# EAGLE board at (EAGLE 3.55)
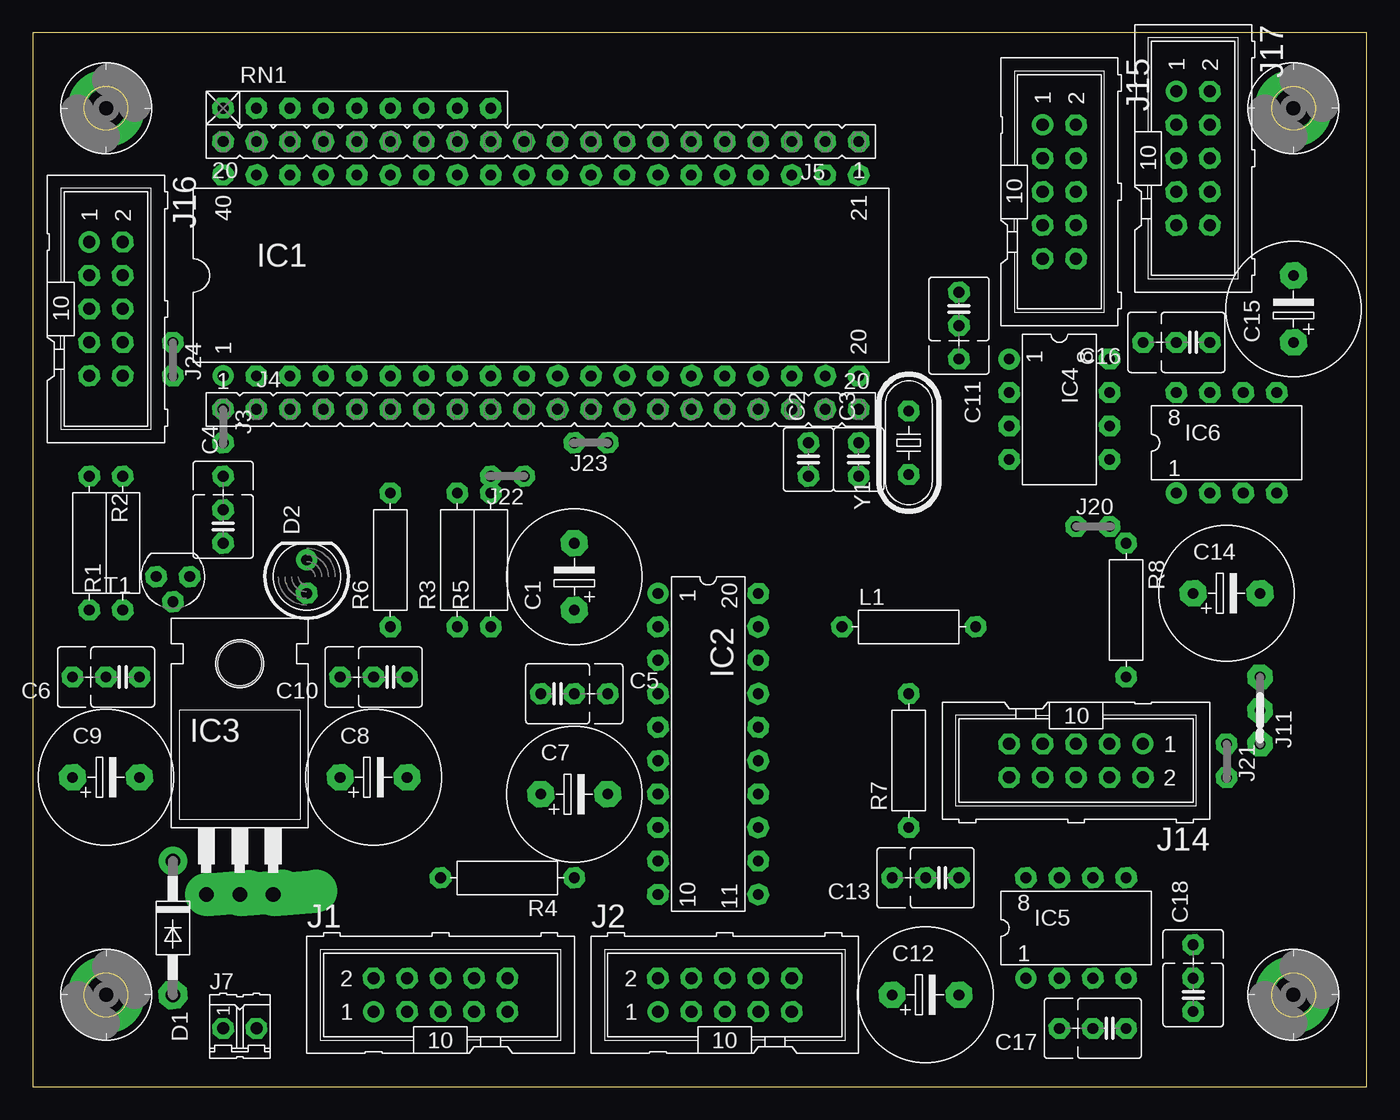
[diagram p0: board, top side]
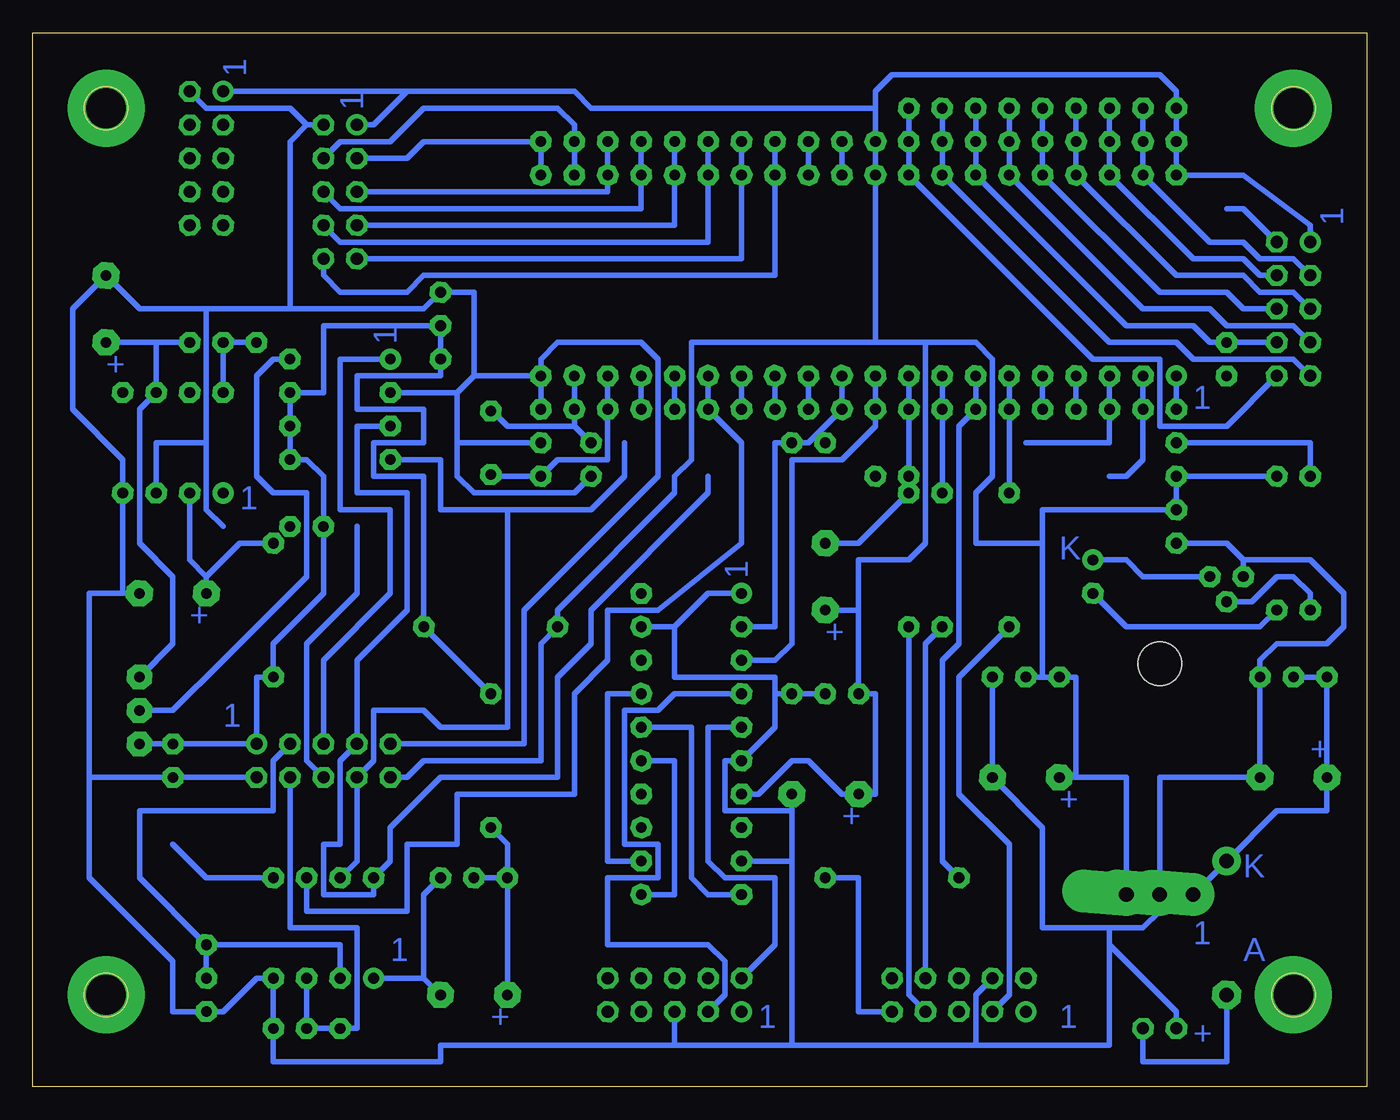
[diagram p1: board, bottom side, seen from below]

Size 101.27 x 80 mm. Coordinates in mm from the lower left corner, seen from the top.
Outline: 0,0 101.27,0 101.27,80 0,80 0,0
Copper layers used: Bottom

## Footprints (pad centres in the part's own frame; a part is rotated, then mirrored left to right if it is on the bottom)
-5 = drill 0.813 pad 2.007 octagon:  -2.54,0;  2.54,0
,5-4 = drill 0.813 pad 1.6 octagon:  -1.27,0;  1.27,0
,5/5-5 = drill 0.813 pad 1.6 octagon:  -2.54,0;  2.54,0;  0,0
41-10 = drill 1.118 pad 2.159 octagon:  5.08,0 | drill 1.118 pad 2.159 round:  -5.08,0
D5 = drill 0.813 pad 1.6 octagon:  -1.27,0 | drill 0.813 pad 1.6 round:  1.27,0
L40 = drill 0.813 pad 1.6 round:  -24.13,-7.62 | drill 0.813 pad 1.6 octagon:  -21.59,-7.62;  -19.05,-7.62;  -16.51,-7.62;  -13.97,-7.62;  -11.43,-7.62;  -8.89,-7.62;  -6.35,-7.62;  -3.81,-7.62;  -1.27,-7.62;  1.27,-7.62;  3.81,-7.62;  6.35,-7.62;  8.89,-7.62;  11.43,-7.62;  13.97,-7.62;  16.51,-7.62;  19.05,-7.62;  21.59,-7.62;  24.13,-7.62;  24.13,7.62;  21.59,7.62;  19.05,7.62;  16.51,7.62;  13.97,7.62;  11.43,7.62;  8.89,7.62;  6.35,7.62;  3.81,7.62;  1.27,7.62;  -1.27,7.62;  -3.81,7.62;  -6.35,7.62;  -8.89,7.62;  -11.43,7.62;  -13.97,7.62;  -16.51,7.62;  -19.05,7.62;  -21.59,7.62;  -24.13,7.62
L20 = drill 0.813 pad 1.6 round:  -11.43,-3.81 | drill 0.813 pad 1.6 octagon:  -8.89,-3.81;  -6.35,-3.81;  -3.81,-3.81;  -1.27,-3.81;  1.27,-3.81;  3.81,-3.81;  6.35,-3.81;  8.89,-3.81;  11.43,-3.81;  11.43,3.81;  8.89,3.81;  6.35,3.81;  3.81,3.81;  1.27,3.81;  -1.27,3.81;  -3.81,3.81;  -6.35,3.81;  -8.89,3.81;  -11.43,3.81
220H = drill 1.118 pad 3.251 offset:  -2.54,-6.35;  0,-6.35;  2.54,-6.35 | hole 3.302: 0,11.176
L08 = drill 0.813 pad 1.6 round:  -3.81,-3.81 | drill 0.813 pad 1.6 octagon:  -1.27,-3.81;  1.27,-3.81;  3.81,-3.81;  3.81,3.81;  1.27,3.81;  -1.27,3.81;  -3.81,3.81
10 = drill 0.914 pad 1.6 round:  -5.08,-1.27 | drill 0.914 pad 1.6 octagon:  -5.08,1.27;  -2.54,-1.27;  -2.54,1.27;  0,-1.27;  0,1.27;  2.54,-1.27;  2.54,1.27;  5.08,-1.27;  5.08,1.27
 = drill 0.813 pad 1.6 octagon:  -2.54,0;  0,0
20 = drill 0.813 pad 1.6 octagon:  -24.13,0;  -21.59,0;  -19.05,0;  -16.51,0;  -13.97,0;  -11.43,0;  -8.89,0;  -6.35,0;  -3.81,0;  -1.27,0;  1.27,0;  3.81,0;  6.35,0;  8.89,0;  11.43,0;  13.97,0;  16.51,0;  19.05,0;  21.59,0;  24.13,0
P = drill 0.914 pad 1.6 octagon:  -1.27,0;  1.27,0
C = drill 0.813 pad 1.905 octagon:  -5.08,0;  -2.54,0;  0,0
10' = drill 0.813 pad 1.6 octagon:  -5.08,0;  5.08,0
3,0-P = drill 3.023 pad 5.842 round: 0 0,0
-9 = drill 0.813 pad 1.6 octagon:  -10.16,0;  -7.62,0;  -5.08,0;  -2.54,0;  0,0;  2.54,0;  5.08,0;  7.62,0;  10.16,0
T54A = drill 0.813 pad 1.6 octagon:  -1.27,0;  0,1.905;  1.27,0
49U-V = drill 0.813 pad 1.6 octagon:  -2.413,0;  2.413,0

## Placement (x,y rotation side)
C1  1u/6.3  [-5]  41.11,38.73 90 top
C2  33p  [,5-4]  58.89,47.62 90 top
C3  33p  [,5-4]  62.7,47.62 90 top
C4  100n  [,5/5-5]  14.44,43.81 90 top
C5  100n  [,5/5-5]  41.11,29.84 0 top
C6  100n  [,5/5-5]  5.55,31.11 180 top
C7  1u/6.3  [-5]  41.11,22.22 0 top
C8  4.7u/6.3  [-5]  25.87,23.49 0 top
C9  100u/35  [-5]  5.55,23.49 0 top
C10  100n  [,5/5-5]  25.87,31.11 180 top
C11  100n  [,5/5-5]  70.32,57.78 270 top
C12  1u/6.3  [-5]  67.78,6.98 0 top
C13  100n  [,5/5-5]  67.78,15.87 180 top
C14  100u/35  [-5]  90.64,37.46 0 top
C15  4u7/6.3  [-5]  95.72,59.05 90 top
C16  47n  [,5/5-5]  86.83,56.51 180 top
C17  100n  [,5/5-5]  80.48,4.44 180 top
C18  100n  [,5/5-5]  88.1,8.25 90 top
D1  1N4001  [41-10]  10.63,12.06 270 top
D2  LED5mm,grn  [D5]  20.79,38.73 90 top
IC1  AT89C8252  [L40]  38.57,61.59 0 top
IC2  MAX233CPP  [L20]  51.27,26.03 270 top
IC3  7805  [220H]  15.71,20.95 0 top
IC4  MAX517ACPA  [L08]  77.94,51.43 270 top
IC5  MAX144ACP  [L08]  79.21,12.06 0 top
IC6  MAX874CPA  [L08]  90.64,48.89 0 top
J1  10pol/Wanne  [10]  30.95,6.98 0 top
J2  10pol/Wanne  [10]  52.54,6.98 0 top
J3  Jumper  []  14.44,48.89 270 top
J4  20pol  [20]  38.57,51.43 0 top
J5  20pol  [20]  38.57,71.75 180 top
J7  Buchse  [P]  15.71,4.44 0 top
J11  Jumper  [C]  93.18,26.03 270 top
J14  10pol/Wanne  [10]  79.21,24.76 180 top
J15  10pol/Wanne  [10]  77.94,67.94 270 top
J16  10pol/Wanne  [10]  5.55,59.05 270 top
J17  10pol/Wanne  [10]  88.1,70.48 270 top
J20  Br10  []  81.75,42.54 0 top
J21  Br10  []  90.64,23.49 270 top
J22  Br30  []  34.76,46.35 180 top
J23  Br30  []  41.11,48.89 180 top
J24  Br25  []  10.63,53.97 270 top
L1  3u3  [10']  66.51,34.92 0 top
PAD1  BO3,0P  [3,0-P]  95.72,6.98 0 top
PAD2  BO3,0P  [3,0-P]  5.55,6.98 0 top
PAD3  BO3,0P  [3,0-P]  95.72,74.29 0 top
PAD4  BO3,0P  [3,0-P]  5.55,74.29 180 top
R1  470  [10']  6.82,41.27 90 top
R2  10K  [10']  4.28,41.27 270 top
R3  330  [10']  32.22,40 90 top
R4  330  [10']  36.03,15.87 180 top
R5  330  [10']  34.76,40 90 top
R6  330  [10']  27.14,40 90 top
R7  10  [10']  66.51,24.76 90 top
R8  150  [10']  83.02,36.19 270 top
RN1  22Kx8  [-9]  24.6,74.29 0 top
T1  BC547C  [T54A]  10.63,38.73 180 top
Y1  24MHz  [49U-V]  66.51,48.89 90 top

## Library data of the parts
C1 C7-C9 C12 C14 C15 L1 R1-R8 RN1 = DISCRETE
C2-C6 C10 C11 C13 C16-C18 = CAP
D1 = DIODE
D2 = LED
IC1 = INTEL
IC2 IC4-IC6 = maximnew
IC3 = LINEAR
J1 J2 J14-J17 = CON-ML
J3 J11 J20-J24 = JUMPER-r
J4 J5 = CON-LSTA
J7 = CONQUICK
PAD1-PAD4 = HOLES
T1 = TRANS-SM
Y1 = QUARTZ

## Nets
+5V: C11. IC4. J11. J14. L1. R7. R8.
GND: C2. C3. C4. C5. C6. C7. C8. C9. C10. C11. C14. C15. C17. C18. IC1. IC2. IC3. IC4. IC5. IC6. J1. J2. J4. J7. J14. J15. J17. J20. J24. T1.
N$1: C2. IC1. J4. Y1.
N$2: C3. IC1. J4. Y1.
N$3: IC1. J5.
N$4: IC1. J5.
N$5: IC2.
N$6: IC2.
N$7: D2. R1.
N$8: IC2.
N$9: C18. IC5. J14.
N$10: IC4. J11. J21.
N$11: IC5. J21.
N$12: IC2. J2.
N$13: J1. R6.
N$14: J1. R3.
N$15: J1. R5.
N$16: D2. T1.
N$17: R2. T1.
N$18: J3. R2.
N$19: IC2. J2.
N$20: C17. IC5. J14.
N$21: J1. R4.
N$22: C12. C13. R7.
N$23: D1. J7.
N$24: C6. C9. D1. IC3.
N$25: C12. C13. IC5.
N$26: C14. IC6. R8.
N$28: J16. J24.
N$29: C15. C16. IC6. J11.
N$30: C16. IC6.
N$32: J14. J20.
N$33: IC4. IC5. J14. J22.
N$34: IC4. IC5. J14. J23.
N$35: IC4. J14.
P00: IC1. J5. J16. RN1.
P01: IC1. J5. J16. RN1.
P02: IC1. J5. J16. RN1.
P03: IC1. J5. J16. RN1.
P04: IC1. J5. J16. RN1.
P05: IC1. J5. J16. RN1.
P06: IC1. J5. J16. RN1.
P07: IC1. J5. J16. RN1.
P10: IC1. J3. J4.
P11: IC1. J4. J22.
P12: IC1. J4. J23.
P13: IC1. J4.
P14: IC1. J4.
P15: IC1. J4. R6.
P16: IC1. J4. R4.
P17: IC1. J4. R3.
P20: IC1. J5. J15.
P21: IC1. J5. J15.
P22: IC1. J5. J15.
P23: IC1. J5. J15.
P24: IC1. J5. J15.
P25: IC1. J5. J15.
P26: IC1. J5. J15.
P27: IC1. J5. J15.
P30: IC1. IC2. J4.
P31: IC1. IC2. J4.
P32: IC1. J4.
P33: IC1. J4.
P34: IC1. J4.
P35: IC1. IC5. J4.
P36: IC1. J4.
P37: IC1. J4.
RST: C1. IC1. J4. R5.
VCC: C1. C4. C5. C7. C8. C10. IC1. IC2. IC3. J5. J14. J15. J16. J17. L1. R1. RN1.

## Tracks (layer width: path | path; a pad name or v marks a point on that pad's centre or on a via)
+5V
  Bottom 0.406: J11. 84.29,26.03 84.29,31.11 R8. 83.02,33.65 79.21,37.46 79.21,46.35 80.48,47.62 81.75,47.62 81.75,50.16 81.75,52.7 79.21,52.7 79.21,57.78 | R7. L1. 71.59,46.35 75.4,46.35 75.4,48.89 71.59,48.89 71.59,51.43 76.67,51.43 76.67,53.97 70.32,53.97 70.32,55.24 C11. 79.21,57.78 | 79.21,57.78 77.94,57.78
GND
  Bottom 0.406: 28.41,31.11 C8. 24.6,19.68 24.6,12.06 19.52,12.06 | 14.44,4.44 14.44,5.71 19.52,10.79 | 19.52,10.79 19.52,12.06 | 19.52,12.06 16.98,12.06 15.71,13.33 15.71,14.6 15.71,23.49 C9. 8.09,31.11 8.09,32.38 6.82,33.65 3.01,33.65 1.74,34.92 1.74,37.46 4.28,40 9.36,40 | 58.89,46.35 60.16,45.08 67.78,45.08 69.05,46.35 69.05,48.89 | 69.05,48.89 C3. | 62.7,53.97 J4. | 62.7,53.97 67.78,53.97 | 69.05,52.7 74.13,52.7 | 67.78,53.97 69.05,52.7 | 69.05,52.7 69.05,48.89 | 94.45,37.46 94.45,45.08 94.45,47.62 98.26,51.43 98.26,59.05 C15. 93.18,59.05 88.1,59.05 | 94.45,37.46 C14. | 52.54,34.92 55.08,34.92 | 52.54,34.92 50,37.46 47.46,37.46 | 43.65,17.14 47.46,17.14 | 43.65,17.14 43.65,20.95 | 43.65,20.95 C7. | C5. 43.65,29.84 44.92,29.84 44.92,31.11 | 44.92,31.11 44.92,27.3 47.46,24.76 48.73,24.76 48.73,20.95 43.65,20.95 | 52.54,34.92 52.54,31.11 44.92,31.11 | 52.54,3.17 52.54,5.71 | 29.68,3.17 43.65,3.17 | 43.65,3.17 52.54,3.17 | 29.68,3.17 29.68,6.98 28.41,8.25 | 52.54,3.17 70.32,3.17 70.32,1.9 83.02,1.9 83.02,4.44 83.02,8.25 84.29,8.25 86.83,5.71 | 96.99,23.49 84.29,23.49 | 86.83,5.71 90.64,5.71 90.64,9.52 96.99,15.87 96.99,23.49 | 43.65,3.17 43.65,17.14 | 94.45,37.46 96.99,37.46 96.99,23.49 | 19.52,10.79 19.52,3.17 29.68,3.17 | 86.83,42.54 88.1,43.81 88.1,48.89 | 91.91,45.08 91.91,48.89 88.1,48.89 | 86.83,5.71 88.1,5.71 | 67.78,53.97 67.78,60.32 70.32,60.32 71.59,59.05 81.75,59.05 | 88.1,59.05 88.1,48.89 | 81.75,59.05 81.75,71.75 80.48,73.02 | 80.48,73.02 79.21,73.02 | 74.13,26.03 63.97,26.03 63.97,36.19 53.81,46.35 53.81,55.24 55.08,56.51 61.43,56.51 62.7,55.24 62.7,53.97 | 14.44,41.27 10.63,41.27 9.36,40 | 9.36,40 T1.
  Bottom 0.406: 89.37,75.56 88.1,74.29 81.75,74.29 80.48,73.02 | 88.1,59.05 81.75,59.05
N$1
  Bottom 0.406: 60.16,50.16 60.16,51.43 60.16,53.97 | C2. 60.16,50.16 | 60.16,50.16 65.24,50.16 66.51,51.43 Y1.
N$2
  Bottom 0.406: 57.62,53.97 57.62,51.43 57.62,47.62 61.43,47.62 62.7,46.35 66.51,46.35 66.51,46.48
N$3
  Bottom 0.406: 42.38,69.21 42.38,71.75
N$4
  Bottom 0.406: 39.84,69.21 39.84,71.75
N$5
  Bottom 0.406: 55.08,14.6 52.54,14.6 52.54,24.76 55.08,24.76
N$6
  Bottom 0.406: 47.46,14.6 50,14.6 51.27,15.87 51.27,27.3 55.08,27.3
N$7
  Bottom 0.406: 6.82,36.19 8.09,34.92 18.25,34.92 20.79,37.46
N$8
  Bottom 0.406: 55.08,17.14 57.62,17.14 57.62,29.84 55.08,29.84
N$9
  Bottom 0.406: 77.94,8.25 77.94,10.79 88.1,10.79 | 81.75,26.03 83.02,24.76 83.02,20.95 93.18,20.95 93.18,15.87 88.1,10.79 | 88.1,10.79 C18.
N$10
  Bottom 0.406: IC4. 83.02,55.24 84.29,53.97 84.29,46.35 83.02,45.08 80.48,45.08 80.48,38.73 86.83,32.38 | 86.83,32.38 84.29,34.92 | 86.83,32.38 90.64,28.57 93.18,28.57
N$11
  Bottom 0.406: 83.02,15.87 88.1,15.87 90.64,18.41
N$12
  Bottom 0.406: 47.46,29.84 52.54,29.84 53.81,28.57 56.35,28.57 56.35,18.41 53.81,18.41 53.81,15.87 57.62,15.87 57.62,10.79 50,10.79 48.73,9.52 48.73,6.98 50,5.71
N$13
  Bottom 0.406: 28.41,5.71 27.14,6.98 27.14,18.41 30.95,22.22 30.95,31.11 27.14,34.92
N$14
  Bottom 0.406: 33.49,8.25 33.49,33.65 32.22,34.92
N$15
  Bottom 0.406: 33.49,5.71 34.76,6.98 34.76,34.92
N$16
  Bottom 0.406: D2. 18.25,40 16.98,38.73 11.9,38.73
N$17
  Bottom 0.406: R2. 4.28,37.46 5.55,38.73 6.82,38.73 8.72,36.83 10.63,36.83
N$18
  Bottom 0.406: J3. 4.28,48.89 4.28,46.35
N$19
  Bottom 0.406: 47.46,8.25 44.92,10.79 44.92,15.87 48.73,15.87 50,17.14 50,27.3 47.46,27.3
N$20
  Bottom 0.406: 80.48,8.25 C17. 77.94,4.44 76.67,4.44 76.67,12.06 81.75,12.06 81.75,23.49
N$21
  Bottom 0.406: 36.03,5.71 38.57,5.71 38.57,15.87 41.11,15.87
N$22
  Bottom 0.406: 65.24,15.87 C13. | 65.24,15.87 65.24,18.41 66.51,19.68 | 65.24,6.98 65.24,15.87
N$23
  Bottom 0.406: J7. 16.98,1.9 10.63,1.9 10.63,6.98
N$24
  Bottom 0.406: C6. 3.01,31.11 3.01,23.49 3.01,20.95 6.82,20.95 D1. 13.17,14.6
N$25
  Bottom 0.406: C12. 71.59,8.25 | 70.32,15.87 71.59,14.6 71.59,8.25 | 71.59,8.25 75.4,8.25
N$26
  Bottom 0.406: 89.37,45.08 89.37,40 88.1,38.73 | 88.1,38.73 88.1,37.46 | 83.02,41.27 85.56,41.27 88.1,38.73
N$28
  Bottom 0.406: 6.82,64.13 9.36,66.67 10.63,66.67
N$29
  Bottom 0.406: 93.18,31.11 90.64,33.65 90.64,38.73 93.18,41.27 93.18,51.43 91.91,52.7 91.91,56.51 | 91.91,56.51 89.37,56.51 | 91.91,56.51 95.72,56.51
N$30
  Bottom 0.406: IC6. C16. 84.29,56.51
N$32
  Bottom 0.406: 79.21,23.49 80.48,24.76 80.48,33.65 76.67,37.46 76.67,42.54
N$33
  Bottom 0.406: 50,46.35 50,45.08 58.89,36.19 58.89,33.65 61.43,31.11 61.43,23.49 70.32,23.49 74.13,19.68 74.13,17.14 IC5. 75.4,14.6 79.21,14.6 79.21,18.41 77.94,18.41 77.94,24.76 76.67,26.03 76.67,32.38 72.86,36.19 72.86,45.08 76.67,45.08 76.67,50.16 74.13,50.16
N$34
  Bottom 0.406: 77.94,15.87 76.67,17.14 76.67,23.49 75.4,24.76 75.4,28.57 71.59,28.57 70.32,27.3 65.24,27.3 65.24,43.81 | 56.35,48.89 56.35,46.35 58.89,43.81 65.24,43.81 | 65.24,43.81 70.32,43.81 70.32,47.62 74.13,47.62
N$35
  Bottom 0.406: 74.13,55.24 77.94,55.24 77.94,43.81 74.13,43.81 74.13,37.46 79.21,32.38 79.21,26.03
P00
  Bottom 0.406: 16.98,69.21 16.98,71.75 16.98,74.29 16.98,69.21 | 16.98,69.21 11.9,64.13 9.36,64.13 8.09,62.86 5.55,62.86 4.28,61.59
P01
  Bottom 0.406: 19.52,74.29 19.52,71.75 19.52,69.21 13.17,62.86 9.36,62.86 8.09,61.59 6.82,61.59
P02
  Bottom 0.406: 22.06,74.29 22.06,71.75 22.06,69.21 14.44,61.59 9.36,61.59 8.09,60.32 5.55,60.32 4.28,59.05
P03
  Bottom 0.406: 24.6,74.29 24.6,71.75 24.6,69.21 15.71,60.32 10.63,60.32 9.36,59.05 6.82,59.05
P04
  Bottom 0.406: 27.14,74.29 27.14,71.75 27.14,69.21 16.98,59.05 11.9,59.05 10.63,57.78 5.55,57.78 4.28,56.51
P05
  Bottom 0.406: 29.68,74.29 29.68,71.75 29.68,69.21 18.25,57.78 13.17,57.78 11.9,56.51 6.82,56.51
P06
  Bottom 0.406: 32.22,74.29 32.22,71.75 32.22,69.21 19.52,56.51 14.44,56.51 13.17,55.24 5.55,55.24 4.28,53.97
P07
  Bottom 0.406: RN1. 34.76,71.75 34.76,69.21 20.79,55.24 15.71,55.24 15.71,50.16 10.63,50.16 J16.
P10
  Bottom 0.406: 14.44,51.43 14.44,53.97
P11
  Bottom 0.406: 19.52,46.35 18.25,46.35 16.98,47.62 16.98,51.43 16.98,53.97
P12
  Bottom 0.406: 25.87,48.89 19.52,48.89 19.52,51.43 19.52,53.97
P13
  Bottom 0.406: 22.06,51.43 22.06,53.97
P14
  Bottom 0.406: 24.6,51.43 24.6,53.97
P15
  Bottom 0.406: R6. 27.14,51.43 27.14,53.97
P16
  Bottom 0.406: 29.68,53.97 29.68,51.43 30.95,50.16 30.95,33.65 32.22,32.38 32.22,17.14 R4.
P17
  Bottom 0.406: R3. 32.22,51.43 32.22,53.97
P20
  Bottom 0.406: 62.7,69.21 62.7,71.75 71.59,71.75 72.86,70.48 76.67,70.48
P21
  Bottom 0.406: 60.16,71.75 60.16,69.21 60.16,73.02 61.43,74.29 71.59,74.29 74.13,71.75 77.94,71.75 79.21,70.48
P22
  Bottom 0.406: 57.62,71.75 57.62,69.21 57.62,67.94 76.67,67.94
P23
  Bottom 0.406: 55.08,71.75 55.08,69.21 55.08,66.67 77.94,66.67 79.21,67.94
P24
  Bottom 0.406: 52.54,71.75 52.54,69.21 52.54,65.4 76.67,65.4
P25
  Bottom 0.406: 50,71.75 50,69.21 50,64.13 77.94,64.13 79.21,65.4
P26
  Bottom 0.406: 47.46,71.75 47.46,69.21 47.46,62.86 76.67,62.86
P27
  Bottom 0.406: 44.92,71.75 44.92,69.21 44.92,61.59 71.59,61.59 72.86,60.32 77.94,60.32 79.21,61.59 J15.
P30
  Bottom 0.406: 37.3,53.97 37.3,51.43 37.3,50.16 39.84,47.62 43.65,47.62 43.65,33.65 44.92,32.38 47.46,32.38
P31
  Bottom 0.406: 39.84,53.97 39.84,51.43 42.38,48.89 44.92,48.89 44.92,34.92 47.46,34.92
P32
  Bottom 0.406: 42.38,51.43 42.38,53.97
P33
  Bottom 0.406: 44.92,51.43 44.92,53.97
P34
  Bottom 0.406: 47.46,51.43 47.46,53.97
P35
  Bottom 0.406: 50,53.97 50,51.43 47.46,48.89 47.46,41.27 53.81,36.19 57.62,36.19 57.62,32.38 60.16,29.84 60.16,22.22 69.05,22.22 69.05,18.41 72.86,18.41 72.86,13.33 80.48,13.33 80.48,15.87
P36
  Bottom 0.406: 52.54,51.43 52.54,53.97
P37
  Bottom 0.406: 55.08,51.43 55.08,53.97
RST
  Bottom 0.406: 34.76,53.97 34.76,51.43 R5. 38.57,41.27 C1.
VCC
  Bottom 0.406: 24.6,31.11 C10. | 24.6,31.11 23.33,31.11 22.06,31.11 22.06,23.49 | 22.06,23.49 23.33,23.49 | 22.06,23.49 18.25,23.49 IC3. | 38.57,36.19 38.57,29.84 37.3,29.84 37.3,22.22 38.57,22.22 39.84,22.22 42.38,24.76 43.65,24.76 46.19,22.22 47.46,22.22 | 38.57,36.19 41.11,36.19 | J5. IC1. 9.36,69.21 4.28,65.4 4.28,64.13 | J5. 14.44,74.29 | 33.49,56.51 29.68,56.51 28.41,55.24 28.41,46.35 29.68,45.08 29.68,41.27 24.6,41.27 | 33.49,56.51 37.3,56.51 | 37.3,56.51 51.27,56.51 51.27,47.62 52.54,46.35 52.54,45.08 61.43,36.19 61.43,34.92 62.7,33.65 62.7,24.76 71.59,24.76 72.86,23.49 J14. | 38.57,36.19 38.57,40 34.76,40 33.49,41.27 33.49,56.51 | 24.6,31.11 24.6,41.27 | 72.86,75.56 75.4,73.02 76.67,73.02 | 72.86,75.56 60.16,75.56 58.89,74.29 37.3,74.29 | J5. 14.44,75.56 15.71,76.83 36.03,76.83 37.3,75.56 37.3,74.29 | 37.3,74.29 37.3,69.21 37.3,56.51 | 24.6,41.27 24.6,43.81 C4. 14.44,46.35 R1. | 72.86,75.56 86.83,75.56

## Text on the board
Bottom: 1 | 1 | 1 | 1 | + | 1 | 1 | K | 1 | + | + | 1 | + | + | + | K | 1 | A | 1 | 1 | 1 | + | +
